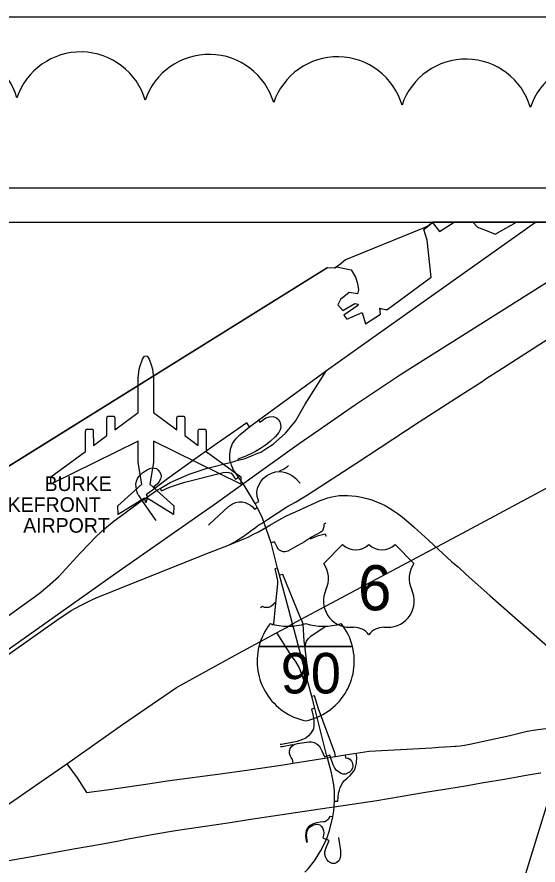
# Model space of a CAD drawing. Extents: x 0 to 96.2, y -27.5 to 31.3.
# Drawn here: x 46.354 to 47.878, y 18.907 to 21.387 of the extents above; entities that cross this region are included whole.
import ezdxf

# ---------------------------------------------------------------- set-up
doc = ezdxf.new("R2010")
doc.units = 0
for name, color, linetype in [('BOTTOM-BLKS', 7, 'Continuous'), ('DIM', 7, 'Continuous'), ('TB1', 7, 'Continuous'), ('TB_INDEX', 7, 'Continuous'), ('TB_PIPEMAT', 7, 'Continuous'), ('TB_PP_30x10_GRID', 7, 'Continuous'), ('TB_PP_50x10_GRID', 7, 'Continuous'), ('TB_PROF_20x5_GRID', 7, 'Continuous'), ('TB_PSDSOD', 7, 'Continuous'), ('TB_PSNSUM', 7, 'Continuous'), ('TB_SIGN_XS', 7, 'Continuous'), ('TB_SIGN_XS_GRID', 7, 'Continuous'), ('TB_SUPER_50x0-5', 7, 'Continuous'), ('TB_SUPER_50x0-5_GRID', 7, 'Continuous'), ('TB_SUPER_50x1', 7, 'Continuous'), ('TB_SUPER_50x1_GRID', 7, 'Continuous')]:
    doc.layers.add(name, color=color, linetype=linetype)

msp = doc.modelspace()

# ---------------------------------------------------------------- linework, layer by layer
at = {"layer": 'BOTTOM-BLKS'}
for points in [[(43.8234, 18.3711), (43.8234, 13.9869), (50.6234, 13.9869), (50.6234, 20.7869), (47.5697, 20.7869)], [(47.5697, 20.7869), (47.5549, 20.7755), (47.5401, 20.7686), (47.3142, 20.6769), (47.2957, 20.6616), (47.2821, 20.6527), (47.2613, 20.6537), (46.0779, 19.9176), (45.8857, 19.6966), (45.2991, 19.2457), (45.2981, 19.2331), (45.2884, 19.2171), (45.2624, 19.1925), (45.2337, 19.1699), (45.2098, 19.1632), (45.181, 19.166), (45.1439, 19.1425), (45.1344, 19.0097), (45.1214, 18.9823), (45.0939, 18.9569), (45.0625, 18.9403), (45.0216, 18.9255), (44.9794, 18.9013)]]:
    msp.add_lwpolyline(points, dxfattribs=at)
at = {"layer": 'DIM'}
msp.add_lwpolyline([(43.2234, 21.3869), (74.7234, 21.3869), (74.7234, 0.3869), (43.2234, 0.3869)], close=True, dxfattribs=at)
at = {"layer": 'TB1'}
for p, q in [((43.7234, 20.8869), (50.7234, 20.8869)), ((43.8234, 20.7869), (50.6234, 20.7869))]:
    msp.add_line(p, q, dxfattribs=at)
at = {"layer": 'TB_INDEX'}
msp.add_line((47.4134, 20.5348), (47.4346, 20.5313), dxfattribs=at)
at = {"layer": 'TB_PIPEMAT'}
for points in [[(47.288, 20.6565), (47.331, 20.6477), (47.3435, 20.6266), (47.3495, 20.608), (47.3528, 20.5895), (47.35, 20.5772), (47.3252, 20.581), (47.3001, 20.5609), (47.2924, 20.5456), (47.3071, 20.529), (47.3421, 20.549), (47.3512, 20.5476), (47.3505, 20.543), (47.3099, 20.5154), (47.3181, 20.503), (47.363, 20.5227), (47.373, 20.4894), (47.4167, 20.5178), (47.4149, 20.5352), (47.4355, 20.5302), (47.5647, 20.6261), (47.5531, 20.7347), (47.5431, 20.7654), (47.5686, 20.7863), (47.5895, 20.7596), (47.6321, 20.7869)], [(47.288, 20.6565), (47.331, 20.6477), (47.3435, 20.6266), (47.3495, 20.608), (47.3528, 20.5895), (47.35, 20.5772), (47.3252, 20.581), (47.3001, 20.5609), (47.2924, 20.5456), (47.3071, 20.529), (47.3421, 20.549), (47.3512, 20.5476), (47.3505, 20.543), (47.3099, 20.5154), (47.3181, 20.503), (47.363, 20.5227), (47.373, 20.4894), (47.4167, 20.5178), (47.4149, 20.5352), (47.4355, 20.5302), (47.5647, 20.6261), (47.5531, 20.7347), (47.5431, 20.7654), (47.5686, 20.7863), (47.5895, 20.7596), (47.6321, 20.7869)], [(47.288, 20.6565), (47.331, 20.6477), (47.3435, 20.6266), (47.3495, 20.608), (47.3528, 20.5895), (47.35, 20.5772), (47.3252, 20.581), (47.3001, 20.5609), (47.2924, 20.5456), (47.3071, 20.529), (47.3421, 20.549), (47.3512, 20.5476), (47.3505, 20.543), (47.3099, 20.5154), (47.3181, 20.503), (47.363, 20.5227), (47.373, 20.4894), (47.4167, 20.5178), (47.4149, 20.5352), (47.4355, 20.5302), (47.5647, 20.6261), (47.5531, 20.7347), (47.5431, 20.7654), (47.5686, 20.7863), (47.5895, 20.7596), (47.6321, 20.7869)], [(47.6867, 20.7869), (47.7003, 20.7719), (47.7236, 20.7632), (47.7523, 20.7518), (47.8149, 20.7869)], [(47.6867, 20.7869), (47.7003, 20.7719), (47.7236, 20.7632), (47.7523, 20.7518), (47.8149, 20.7869)], [(47.6867, 20.7869), (47.7003, 20.7719), (47.7236, 20.7632), (47.7523, 20.7518), (47.8149, 20.7869)], [(46.0911, 19.9258), (47.2621, 20.6542), (47.283, 20.6532), (47.288, 20.6565)]]:
    msp.add_lwpolyline(points, dxfattribs=at)
at = {"layer": 'TB_PP_50x10_GRID'}
for points in [[(45.9055, 19.2703), (46.0888, 19.3884), (46.2568, 19.4882), (46.6429, 19.7608), (46.9371, 19.9661), (47.0729, 20.0637), (47.1791, 20.1395), (47.2478, 20.1879), (47.3438, 20.2535), (47.478, 20.3432), (47.913, 20.6171), (48.0033, 20.6774)], [(46.9722, 19.8425), (46.9907, 19.8527), (47.0024, 19.8599), (47.0148, 19.868), (47.0255, 19.8759), (47.0377, 19.8848), (47.051, 19.8944), (47.0613, 19.9019), (47.0686, 19.9064), (47.0864, 19.918), (47.1426, 19.9547), (47.156, 19.9619), (47.1686, 19.968), (47.2032, 19.9899), (47.3448, 20.0818), (47.4163, 20.1282), (47.53, 20.203), (47.6528, 20.2822), (47.7141, 20.3208), (47.726, 20.3296), (47.7731, 20.3597), (47.9208, 20.455)], [(46.9722, 19.8425), (47.0106, 19.8577), (47.0299, 19.8664), (47.0456, 19.8743), (47.0601, 19.8819), (47.095, 19.9021), (47.1269, 19.9202), (47.1397, 19.9271), (47.1543, 19.9342), (47.168, 19.9404), (47.194, 19.9521), (47.2257, 19.9665), (47.2401, 19.9728), (47.2522, 19.9774), (47.2631, 19.9811), (47.2741, 19.9841), (47.2853, 19.986), (47.2963, 19.9875), (47.308, 19.9882), (47.3211, 19.9882), (47.3334, 19.9873), (47.3461, 19.9858), (47.361, 19.9832), (47.3764, 19.9793), (47.3911, 19.9747), (47.4055, 19.9697), (47.4173, 19.9647), (47.43, 19.9584), (47.4432, 19.9509), (47.4566, 19.9421), (47.4658, 19.9358), (47.4765, 19.928), (47.4865, 19.9198), (47.4997, 19.9089), (47.5155, 19.8951), (47.5583, 19.8558), (47.6257, 19.794), (47.6446, 19.7779), (47.6668, 19.7579), (47.7374, 19.6949), (47.9303, 19.5253)], [(45.5238, 19.0447), (45.7156, 19.1389), (45.7618, 19.165), (45.8095, 19.1926), (46.0898, 19.368), (46.2526, 19.4701), (46.4704, 19.6234), (46.5126, 19.6515), (46.5391, 19.6663), (46.5763, 19.6846), (46.6015, 19.6954), (46.6221, 19.7035), (46.6462, 19.7132), (46.9167, 19.8209), (46.9722, 19.8425)]]:
    msp.add_lwpolyline(points, dxfattribs=at)
at = {"layer": 'TB_PROF_20x5_GRID'}
for points in [[(47.06, 20.2083), (47.0641, 20.2026), (47.0817, 20.2147), (47.0926, 20.2182), (47.1026, 20.2185), (47.1126, 20.2151), (47.1191, 20.2089), (47.1236, 20.2002), (47.1253, 20.1897), (47.1235, 20.18), (47.1194, 20.1717), (47.1086, 20.1596), (47.0944, 20.1461), (47.0803, 20.1346), (47.0662, 20.1253), (47.0513, 20.1161), (47.0393, 20.1101), (47.0232, 20.1027), (46.9999, 20.0944), (47.0009, 20.0908)], [(47.0336, 20.1889), (47.0257, 20.1999), (46.9403, 20.1408), (46.8741, 20.0936), (46.7939, 20.0362), (46.7564, 20.0086), (46.7312, 19.9901), (46.735, 19.984)], [(46.7607, 19.9146), (46.7583, 19.9187), (46.7197, 19.9731), (46.7106, 19.9865), (46.7076, 19.9911), (46.7052, 19.9976), (46.7033, 20.0054), (46.7019, 20.0129), (46.7017, 20.0205), (46.7033, 20.0296), (46.7063, 20.0371), (46.7105, 20.0435), (46.7158, 20.0496), (46.7221, 20.0552), (46.7341, 20.0628), (46.7419, 20.0666), (46.749, 20.0683), (46.7552, 20.0681), (46.7618, 20.0663), (46.7669, 20.0622), (46.7709, 20.0573), (46.7744, 20.0504), (46.7751, 20.0433), (46.7738, 20.0354), (46.7695, 20.0283), (46.7644, 20.0223), (46.7598, 20.0179), (46.7538, 20.0127), (46.7564, 20.0086)], [(47.1232, 20.0575), (47.1236, 20.0607), (47.1328, 20.0645), (47.1452, 20.073), (47.1481, 20.0752)], [(46.7724, 20.0084), (46.776, 20.0014), (46.7999, 20.0119), (46.8228, 20.0201), (46.8447, 20.0263), (46.9571, 20.055), (46.9677, 20.0561), (46.9737, 20.0553), (46.98, 20.053), (46.9852, 20.0475), (46.9903, 20.0399), (46.9931, 20.0358), (47.0016, 20.0412)], [(47.0507, 19.9641), (47.0613, 19.9703), (47.0557, 19.9846), (47.0549, 19.9974), (47.0572, 20.0094), (47.0615, 20.0196), (47.0672, 20.0291), (47.075, 20.0388), (47.0831, 20.0454), (47.0921, 20.0506), (47.1006, 20.054), (47.11, 20.0565), (47.1209, 20.0578), (47.1232, 20.0575), (47.1301, 20.0565), (47.1389, 20.0546), (47.1503, 20.0501), (47.1596, 20.045), (47.169, 20.0373), (47.1766, 20.0289), (47.1814, 20.0235)], [(46.9137, 19.901), (46.9168, 19.9039), (46.972, 19.9557), (46.9841, 19.9637), (46.9942, 19.9675), (47.0027, 19.9692), (47.0124, 19.969), (47.0213, 19.9671), (47.0284, 19.9634), (47.0362, 19.9595), (47.0428, 19.9549), (47.0482, 19.9479), (47.0563, 19.9524)], [(47.2565, 19.9067), (47.2512, 19.9031), (47.251, 19.8959), (47.2492, 19.89), (47.2467, 19.8849), (47.242, 19.8808), (47.2147, 19.8656), (47.2088, 19.8619), (47.1946, 19.8528), (47.1658, 19.8363), (47.1457, 19.8255), (47.1423, 19.8241), (47.1381, 19.823), (47.1351, 19.8228), (47.1322, 19.823), (47.1294, 19.8237), (47.1271, 19.8247), (47.1211, 19.8281), (47.1171, 19.8319), (47.1142, 19.8363), (47.1071, 19.8519), (47.0973, 19.8491)], [(47.2593, 19.8681), (47.2551, 19.8746), (47.2316, 19.8686), (47.2224, 19.8647), (47.2101, 19.8599), (47.2088, 19.8619)], [(47.116, 19.775), (47.1081, 19.7729), (47.1087, 19.7702), (47.1153, 19.7382), (47.1152, 19.7296), (47.1097, 19.6729), (47.1036, 19.6114), (47.0988, 19.6082)], [(47.1851, 19.6261), (47.183, 19.6301), (47.1309, 19.7571), (47.1214, 19.7546)], [(47.1097, 19.6729), (47.1063, 19.6732), (47.1013, 19.6668), (47.0954, 19.6625), (47.0889, 19.6607), (47.0834, 19.66), (47.0778, 19.6607), (47.0717, 19.663), (47.0663, 19.6594)], [(47.1995, 19.4623), (47.2075, 19.4643), (47.2015, 19.4997), (47.1952, 19.5494), (47.1935, 19.5622), (47.1906, 19.6114), (47.1891, 19.6176), (47.1872, 19.6221), (47.1851, 19.6261)], [(47.1952, 19.5494), (47.1978, 19.5497), (47.1985, 19.5562), (47.2008, 19.5623), (47.2054, 19.5689), (47.2134, 19.5764), (47.2522, 19.6024), (47.2571, 19.6054)], [(47.113, 19.5858), (47.1133, 19.5852), (47.156, 19.5193), (47.169, 19.5004), (47.1786, 19.484), (47.1929, 19.4473), (47.2028, 19.4498)], [(47.2853, 19.2249), (47.2835, 19.2352), (47.2357, 19.3644), (47.224, 19.4017), (47.2158, 19.3997)], [(47.2245, 19.3657), (47.2149, 19.3633), (47.2197, 19.3426), (47.222, 19.3286), (47.2218, 19.3155), (47.2205, 19.3054), (47.2132, 19.2926), (47.2067, 19.2848), (47.1981, 19.278), (47.1884, 19.274), (47.1732, 19.2684), (47.1276, 19.26), (47.1237, 19.2594)], [(47.1615, 19.2051), (47.1597, 19.2164), (47.1557, 19.2219), (47.1525, 19.2273), (47.1504, 19.2335), (47.1505, 19.2394), (47.1531, 19.2479), (47.1579, 19.2549), (47.1613, 19.2574), (47.167, 19.261), (47.1742, 19.2628), (47.2071, 19.2679), (47.2148, 19.2679), (47.223, 19.2655), (47.2317, 19.2607), (47.2372, 19.2555), (47.2413, 19.2491), (47.2456, 19.2412), (47.2527, 19.224), (47.2603, 19.2259)], [(47.1247, 19.2536), (47.1289, 19.2542), (47.1592, 19.2601), (47.1613, 19.2574)], [(47.3131, 19.2291), (47.3145, 19.2204), (47.3218, 19.2197), (47.3269, 19.2171), (47.3321, 19.2115), (47.335, 19.2054), (47.3361, 19.1967), (47.3346, 19.1902), (47.3313, 19.1838), (47.3265, 19.1785), (47.3207, 19.1755), (47.3141, 19.1733), (47.3078, 19.1735), (47.3013, 19.1751), (47.2942, 19.1795), (47.2876, 19.185), (47.2823, 19.1923), (47.2784, 19.2005), (47.2707, 19.2226), (47.2688, 19.2281), (47.2603, 19.2259)], [(47.2824, 19.0939), (47.2919, 19.0941), (47.2928, 19.106), (47.2944, 19.1176), (47.2965, 19.1259), (47.2993, 19.1339), (47.3025, 19.1412), (47.306, 19.148), (47.3114, 19.1546), (47.3191, 19.1614), (47.3282, 19.1691), (47.3343, 19.1763), (47.3405, 19.1851), (47.3441, 19.1931), (47.3462, 19.2048), (47.3471, 19.2227), (47.3453, 19.2341)], [(47.277, 19.0485), (47.2684, 19.0497), (47.2635, 19.0407), (47.2586, 19.0363), (47.2541, 19.034), (47.2494, 19.0337), (47.2404, 19.0325), (47.23, 19.0303), (47.2177, 19.0267), (47.2113, 19.0234), (47.2054, 19.0183), (47.2012, 19.0123), (47.1992, 19.0071), (47.198, 19.0012), (47.1976, 18.9938), (47.1991, 18.9795), (47.2001, 18.9732)], [(47.2037, 18.9738), (47.2027, 18.9801), (47.2008, 18.9948), (47.201, 19.0012), (47.2021, 19.0064), (47.2054, 19.0129), (47.2082, 19.0172), (47.2136, 19.0214), (47.219, 19.0237), (47.2259, 19.026), (47.2323, 19.0267), (47.239, 19.0245), (47.2442, 19.0204), (47.248, 19.0142), (47.2502, 19.0073), (47.2508, 19.0013), (47.2502, 18.9947), (47.2481, 18.987), (47.2584, 18.9823)], [(47.2939, 18.9881), (47.295, 18.9815), (47.2995, 18.9502), (47.2999, 18.9343), (47.2979, 18.9256), (47.2945, 18.9195), (47.2892, 18.9144), (47.2833, 18.9122), (47.2765, 18.912), (47.2706, 18.9141), (47.2648, 18.918), (47.2594, 18.924), (47.2559, 18.9309), (47.2544, 18.9386), (47.2543, 18.9462), (47.258, 18.9582), (47.2662, 18.9787), (47.2584, 18.9823)]]:
    msp.add_lwpolyline(points, dxfattribs=at)
at = {"layer": 'TB_PSDSOD'}
for points in [[(47.0846, 20.1261), (47.1028, 20.1377), (47.1394, 20.1698), (47.1683, 20.2054), (47.196, 20.2549), (47.2584, 20.3533)], [(46.9221, 20.0705), (46.9688, 20.0821), (46.9786, 20.0847), (47.0009, 20.0908), (47.0212, 20.0963), (47.0581, 20.1113)], [(47.0581, 20.1113), (47.0672, 20.1149), (47.0846, 20.1261)], [(46.6779, 19.9434), (46.7162, 19.971), (46.7173, 19.9718), (46.7197, 19.9731), (46.735, 19.984), (46.759, 20.0005), (46.7724, 20.0084), (46.802, 20.0259), (46.8571, 20.0504), (46.8927, 20.0621)], [(46.8927, 20.0621), (46.9067, 20.0667), (46.9221, 20.0705)], [(46.3027, 19.6188), (46.4181, 19.7014), (46.4434, 19.7217), (46.4749, 19.7497), (46.5398, 19.8203), (46.5853, 19.8679), (46.6096, 19.8906), (46.6375, 19.9139), (46.6726, 19.9395), (46.6779, 19.9434)]]:
    msp.add_lwpolyline(points, dxfattribs=at)
at = {"layer": 'TB_PSNSUM'}
for points in [[(47.3574, 20.4235), (47.8698, 20.7869)], [(47.2584, 20.3533), (47.3574, 20.4235)], [(46.9967, 20.1568), (47.0062, 20.1662), (47.0336, 20.1889), (47.06, 20.2083), (47.2584, 20.3533)], [(46.9787, 20.0841), (46.9786, 20.0847), (46.9765, 20.0928), (46.9762, 20.1069), (46.9782, 20.1228), (46.9841, 20.1396), (46.9936, 20.1538), (46.9967, 20.1568)], [(46.9905, 20.0574), (46.9871, 20.0623), (46.9806, 20.0769), (46.9787, 20.0841)], [(47.1476, 19.6572), (47.1214, 19.7546), (47.116, 19.775), (47.0973, 19.8491), (47.0716, 19.9219), (47.0654, 19.9342), (47.0563, 19.9524), (47.0507, 19.9641), (47.0207, 20.0136), (47.0016, 20.0412), (46.9995, 20.0442), (46.9905, 20.0574)], [(47.1633, 19.5988), (47.1597, 19.6124), (47.1476, 19.6572)], [(47.2627, 19.2166), (47.2614, 19.2212), (47.2603, 19.2259), (47.2245, 19.3657), (47.2158, 19.3997), (47.2104, 19.4211), (47.2028, 19.4498), (47.1995, 19.4623), (47.1633, 19.5988)], [(47.2815, 19.0825), (47.2824, 19.0939), (47.2819, 19.1249), (47.2793, 19.1478), (47.2737, 19.1765), (47.2627, 19.2166)], [(47.1958, 18.8865), (47.2056, 18.8966), (47.2238, 18.9195), (47.2419, 18.9497), (47.2584, 18.9823), (47.2678, 19.008), (47.277, 19.0485), (47.2803, 19.0663), (47.2811, 19.0776), (47.2815, 19.0825)]]:
    msp.add_lwpolyline(points, dxfattribs=at)
at = {"layer": 'TB_SIGN_XS'}
for points in [[(47.1415, 19.602), (47.1597, 19.6124), (47.1851, 19.6261), (47.2289, 19.6496), (47.6709, 19.885), (47.9366, 20.0273), (47.9789, 20.0501), (48.0261, 20.0756), (48.0751, 20.1023), (48.1844, 20.1637), (48.2009, 20.1689)], [(46.4996, 19.2036), (46.6619, 19.3184), (46.715, 19.3541), (46.8201, 19.4264), (47.0022, 19.527), (47.113, 19.5858), (47.1415, 19.602)], [(47.6341, 19.2549), (47.6377, 19.2552), (47.6495, 19.2561), (47.6625, 19.2579), (47.6777, 19.2604), (47.7953, 19.2861), (47.8453, 19.2989), (47.8703, 19.3028), (47.8771, 19.3039), (47.9161, 19.3089), (47.9416, 19.3128), (47.9487, 19.3138)], [(47.3131, 19.2291), (47.3453, 19.2341), (47.3841, 19.24), (47.4379, 19.2428), (47.5674, 19.2504), (47.5862, 19.2516), (47.6049, 19.2531), (47.6216, 19.2537), (47.6341, 19.2549)], [(47.0328, 19.1861), (47.1317, 19.2002), (47.1615, 19.2051), (47.2472, 19.2189)], [(47.2472, 19.2189), (47.2614, 19.2212), (47.2707, 19.2226), (47.2853, 19.2249), (47.3131, 19.2291)], [(46.4334, 19.1578), (46.4996, 19.2036)], [(46.4996, 19.2036), (46.5294, 19.1622), (46.5571, 19.1192)], [(46.6562, 19.1335), (46.7307, 19.1442), (46.7928, 19.1532), (46.9554, 19.1752), (47.0117, 19.1831), (47.0328, 19.1861)], [(47.2664, 19.0754), (47.2811, 19.0776), (47.4061, 19.0963), (47.4742, 19.1074), (47.5484, 19.1201), (47.6165, 19.1312), (47.6657, 19.139), (47.7179, 19.1484), (47.7796, 19.1587), (47.8424, 19.1698), (47.8841, 19.1768), (47.885, 19.1769), (47.8852, 19.1769)], [(46.3093, 19.0718), (46.4274, 19.1536), (46.4334, 19.1578)], [(46.5571, 19.1192), (46.6166, 19.1277)], [(46.6166, 19.1277), (46.6562, 19.1335)], [(46.9769, 19.0321), (47.0305, 19.0401), (47.2664, 19.0754)], [(46.6744, 18.9828), (46.7537, 18.9978), (46.817, 19.0082), (46.9769, 19.0321)], [(46.4021, 18.9331), (46.5188, 18.9548), (46.5989, 18.9688), (46.6518, 18.9785), (46.6744, 18.9828)], [(46.1129, 18.881), (46.1135, 18.8815), (46.2738, 18.9107), (46.4021, 18.9331)]]:
    msp.add_lwpolyline(points, dxfattribs=at)
at = {"layer": 'TB_SIGN_XS_GRID'}
for p, q in [((47.0615, 19.5467), (47.3347, 19.5467)), ((47.3347, 19.5467), (47.0615, 19.5467)), ((47.3347, 19.5467), (47.0615, 19.5467))]:
    msp.add_line(p, q, dxfattribs=at)
for centre, start, end in [((47.2336, 19.5031), 141.669, 165.8066), ((47.1462, 19.7831), 253.0091, 286.9909), ((47.25, 19.7831), 253.0091, 286.9909), ((47.1626, 19.5031), 14.1934, 38.331), ((47.2336, 19.5031), 165.8066, 258.463), ((47.1626, 19.5031), 281.537, 14.1934)]:
    msp.add_arc(centre, 0.1776, start, end, dxfattribs=at)
at = {"layer": 'TB_SUPER_50x0-5'}
for p, q in [((47.3058, 19.8443), (47.2509, 19.7894)), ((47.5145, 19.7894), (47.4596, 19.8443)), ((47.3278, 19.6026), (47.3388, 19.6026)), ((47.4267, 19.6026), (47.4376, 19.6026))]:
    msp.add_line(p, q, dxfattribs=at)
for centre, radius, start, end in [((47.3443, 19.8836), 0.0549, 225.573, 314.427), ((47.4212, 19.8836), 0.0549, 225.573, 314.427), ((47.1879, 19.7453), 0.0769, 334.5471, 35.0009), ((47.5775, 19.7453), 0.0769, 144.9991, 205.4529), ((47.3269, 19.6795), 0.0769, 154.8319, 270.6383), ((47.4385, 19.6795), 0.0769, 269.3617, 25.1681), ((47.3388, 19.5477), 0.0549, 36.8699, 90), ((47.4267, 19.5477), 0.0549, 90, 143.1301)]:
    msp.add_arc(centre, radius, start, end, dxfattribs=at)
at = {"layer": 'TB_SUPER_50x0-5_GRID'}
for points in [[(46.7304, 19.9659), (46.7269, 19.9799), (46.6496, 19.932), (46.6485, 19.958), (46.7191, 20.0213), (46.7077, 20.0843), (46.7077, 20.1468), (46.4527, 20.0212), (46.4527, 20.0419), (46.5541, 20.1169), (46.5541, 20.1752), (46.5559, 20.1814), (46.5755, 20.1814), (46.5769, 20.1783), (46.5773, 20.1341), (46.6165, 20.163), (46.6165, 20.2139), (46.6183, 20.2201), (46.6379, 20.2201), (46.6397, 20.2139), (46.6397, 20.1802), (46.7077, 20.2305), (46.7077, 20.3309), (46.711, 20.3575), (46.7138, 20.367), (46.7206, 20.3863), (46.7269, 20.3949), (46.7304, 20.3964)], [(46.7304, 20.3964), (46.734, 20.3949), (46.7403, 20.3863), (46.7471, 20.367), (46.7499, 20.3575), (46.7532, 20.3309), (46.7532, 20.2305), (46.8212, 20.1802), (46.8212, 20.2139), (46.823, 20.2201), (46.8426, 20.2201), (46.8444, 20.2139), (46.8444, 20.163), (46.8836, 20.1341), (46.884, 20.1783), (46.8854, 20.1814), (46.905, 20.1814), (46.9068, 20.1752), (46.9068, 20.1169), (47.0082, 20.0419), (47.0082, 20.0212), (46.7532, 20.1468), (46.7532, 20.0843), (46.7418, 20.0213), (46.8124, 19.958), (46.8113, 19.932), (46.734, 19.9799), (46.7304, 19.9659)]]:
    msp.add_lwpolyline(points, dxfattribs=at)
at = {"layer": 'TB_SUPER_50x1'}
msp.add_lwpolyline([(48.2252, 20.1257), (47.4236, 17.5299), (48.2252, 19.6035)], close=True, dxfattribs=at)
at = {"layer": 'TB_SUPER_50x1_GRID'}
for centre, start, end in [((46.1648, 21.0949), 16.4231, 161.4231), ((46.5402, 21.0878), 16.4231, 161.4231), ((46.9156, 21.0808), 16.4231, 161.4231), ((47.291, 21.0737), 16.4334, 161.4334), ((47.6664, 21.0669), 16.4698, 161.4698), ((48.0418, 21.0603), 16.5143, 161.5143)]:
    msp.add_arc(centre, 0.1968, start, end, dxfattribs=at)

# ---------------------------------------------------------------- texts
at = {"layer": 'TB_PP_30x10_GRID'}
for s, p in [('BURKE', (46.4344, 20.0008)), ('LAKEFRONT', (46.2569, 19.9399)), ('AIRPORT', (46.3719, 19.8791))]:
    msp.add_text(s, height=0.04261, rotation=0, dxfattribs=at).set_placement(p)
at = {"layer": 'TB_SIGN_XS_GRID'}
msp.add_text('90', height=0.11837, dxfattribs=at).set_placement((47.1251, 19.4091))
at = {"layer": 'TB_SUPER_50x0-5'}
msp.add_text('6', height=0.1318, dxfattribs=at).set_placement((47.3508, 19.6521))

doc.saveas('drawing.dxf')
